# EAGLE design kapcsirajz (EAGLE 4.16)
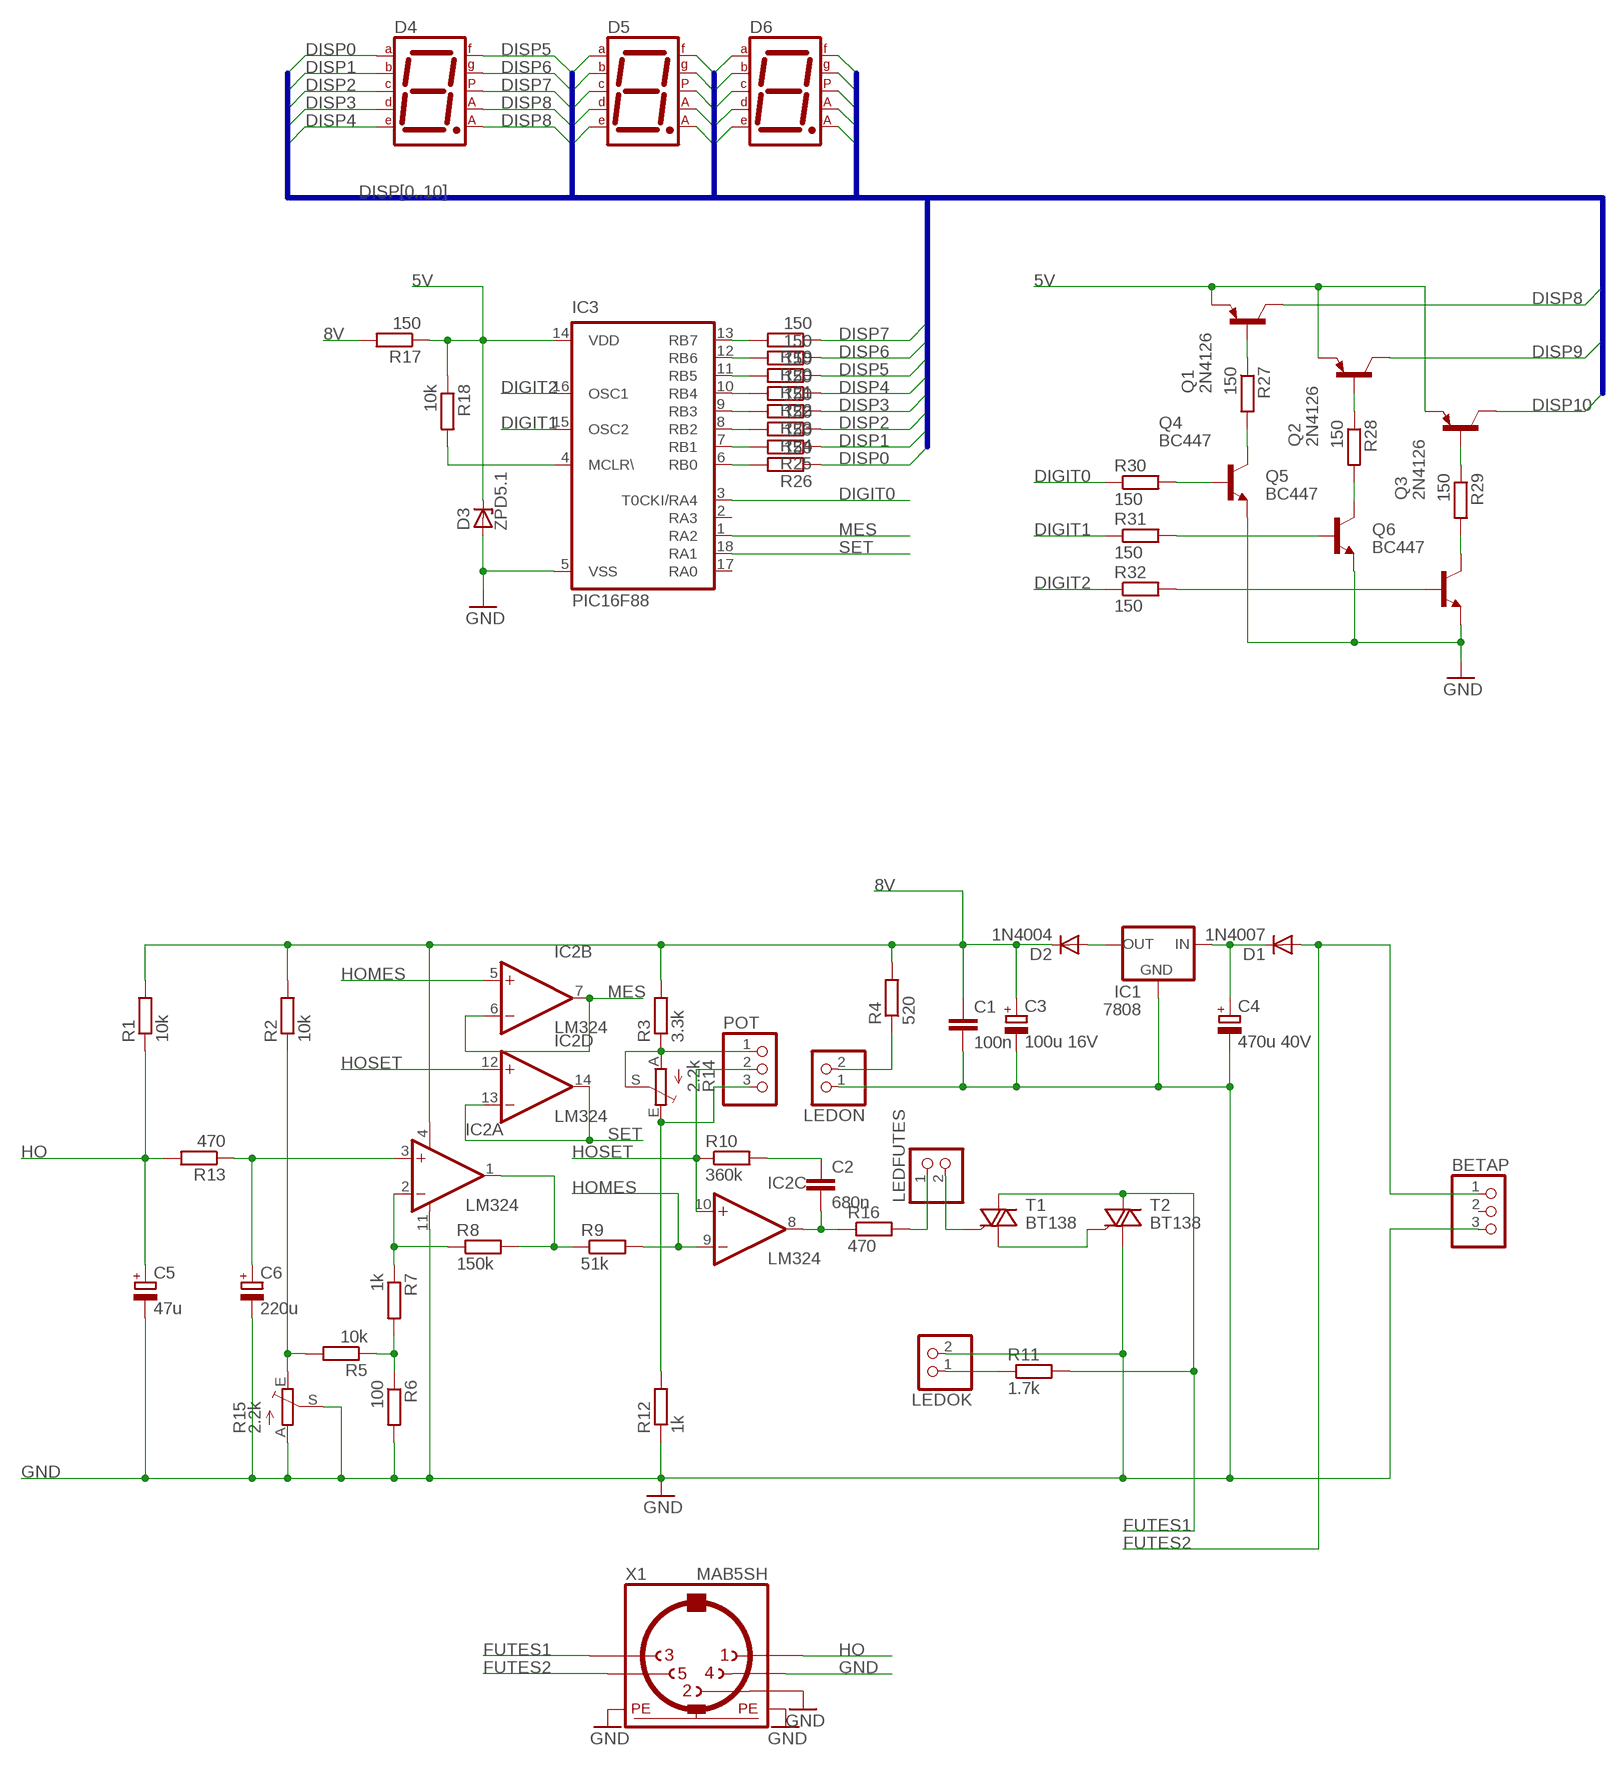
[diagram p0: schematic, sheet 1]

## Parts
BETAP  PINHD-1X3  [1X03]
C1  100n  C-EU025-025X050  [C025-025X050]
C2  680n  C-EU025-025X050  [C025-025X050]
C3  100u 16V  CPOL-EUE2,5-6E  [E2,5-6E]
C4  470u 40V  CPOL-EUE2,5-6E  [E2,5-6E]
C5  47u  CPOL-EUE2,5-6E  [E2,5-6E]
C6  220u  CPOL-EUE2,5-6E  [E2,5-6E]
D1  1N4007  1N4148  [DO35-10]
D2  1N4004  1N4148  [DO35-10]
D3  ZPD5.1  BZD23  [SOD81]
D4  7SEG-CA  [7SEG-13]
D5  7SEG-CA  [7SEG-13]
D6  7SEG-CA  [7SEG-13]
IC1  7808  78XXL  [78XXL]
IC2  LM324  OPA4658UP  [DIL14]
IC3  PIC16F88  PIC16F83SO  [SO-18W]
LEDFUTES  PINHD-1X2  [1X02]
LEDOK  PINHD-1X2  [1X02]
LEDON  PINHD-1X2  [1X02]
POT  PINHD-1X3  [1X03]
Q1  2N4126  [TO92-CBE]
Q2  2N4126  [TO92-CBE]
Q3  2N4126  [TO92-CBE]
Q4  BC447  [TO92-EBC]
Q5  BC447  [TO92-EBC]
Q6  BC447  [TO92-EBC]
R1  10k  R-EU_0204/7  [0204/7]
R2  10k  R-EU_0204/7  [0204/7]
R3  3.3k  R-EU_0204/7  [0204/7]
R4  520  R-EU_0204/7  [0204/7]
R5  10k  R-EU_0204/7  [0204/7]
R6  100  R-EU_0204/7  [0204/7]
R7  1k  R-EU_0204/7  [0204/7]
R8  150k  R-EU_0204/7  [0204/7]
R9  51k  R-EU_0204/7  [0204/7]
R10  360k  R-EU_0204/7  [0204/7]
R11  1.7k  R-EU_0204/7  [0204/7]
R12  1k  R-EU_0204/7  [0204/7]
R13  470  R-EU_0204/7  [0204/7]
R14  2.2k  TRIM_EU-CA6V  [CA6V]
R15  2.2k  TRIM_EU-CA6V  [CA6V]
R16  470  R-EU_0204/7  [0204/7]
R17  150  R-EU_0204/7  [0204/7]
R18  10k  R-EU_0204/7  [0204/7]
R19  150  R-EU_0204/7  [0204/7]
R20  150  R-EU_0204/7  [0204/7]
R21  150  R-EU_0204/7  [0204/7]
R22  150  R-EU_0204/7  [0204/7]
R23  150  R-EU_0204/7  [0204/7]
R24  150  R-EU_0204/7  [0204/7]
R25  150  R-EU_0204/7  [0204/7]
R26  150  R-EU_0204/7  [0204/7]
R27  150  R-EU_0204/7  [0204/7]
R28  150  R-EU_0204/7  [0204/7]
R29  150  R-EU_0204/7  [0204/7]
R30  150  R-EU_0204/7  [0204/7]
R31  150  R-EU_0204/7  [0204/7]
R32  150  R-EU_0204/7  [0204/7]
T1  BT138  TIC225S  [TO220DS]
T2  BT138  TIC225S  [TO220DS]
X1  MAB5SH  [MAB5SH]

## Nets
5V: D3.C IC3.14(VDD) Q1.E Q2.E Q3.E R17.1 R18.1
8V: C1.1 C3.+ D2.C IC2.4(A:V+) R1.2 R2.2 R3.2 R4.2 R17.2
DIGIT0: IC3.3(T0CKI/RA4) R30.1
DIGIT1: IC3.15(OSC2) R31.1
DIGIT2: IC3.16(OSC1) R32.1
DISP0: D4.7(A) D5.7(A) D6.7(A) R26.1
DISP1: D4.6(B) D5.6(B) D6.6(B) R25.1
DISP2: D4.4(C) D5.4(C) D6.4(C) R24.1
DISP3: D4.2(D) D5.2(D) D6.2(D) R23.1
DISP4: D4.1(E) D5.1(E) D6.1(E) R22.1
DISP5: D4.9(F) D5.9(F) D6.9(F) R21.1
DISP6: D4.10(G) D5.10(G) D6.10(G) R20.1
DISP7: D4.5(DP) D5.5(DP) D6.5(DP) R19.1
DISP8: D4.3(CA1) D4.8(CA2) Q1.C
DISP9: D5.3(CA1) D5.8(CA2) Q2.C
DISP10: D6.3(CA1) D6.8(CA2) Q3.C
FUTES1: R11.2 T1.A2 T2.A2 X1.3
FUTES2: BETAP.1 D1.A X1.5
GND: BETAP.3 C1.2 C3.- C4.- C5.- C6.- D3.A IC1.GND IC2.11(A:V-) IC3.5(VSS) LEDOK.2 LEDON.1 Q4.E Q5.E Q6.E R6.2 R12.1 R15.A R15.S T2.A1 X1.2 X1.4 X1.PE X1.PE@(PE)
HO: C5.+ R1.1 R13.2 X1.1
HOMES: IC2.5(B:+IN) IC2.9(C:-IN) R9.2
HOSET: IC2.10(C:+IN) IC2.12(D:+IN) POT.2 R10.1
MES: IC2.6(B:-IN) IC2.7(B:OUT) IC3.1(RA2)
N$1: D2.A IC1.OUT
N$2: C4.+ D1.C IC1.IN
N$3: IC3.4(MCLR\) R18.2
N$4: T1.A1 T2.G
N$5: IC3.13(RB7) R19.2
N$6: POT.1 R3.1 R14.A R14.S
N$7: LEDON.2 R4.1
N$8: POT.3 R12.2 R14.E
N$9: IC2.1(A:OUT) R8.2 R9.1
N$10: IC2.2(A:-IN) R7.1 R8.1
N$11: IC3.12(RB6) R20.2
N$12: R2.1 R5.2 R15.E
N$13: R5.1 R6.1 R7.2
N$14: C6.+ IC2.3(A:+IN) R13.1
N$15: IC3.11(RB5) R21.2
N$16: IC3.10(RB4) R22.2
N$17: C2.2 IC2.8(C:OUT) R16.1
N$18: C2.1 R10.2
N$19: LEDFUTES.1 R16.2
N$20: LEDFUTES.2 T1.G
N$21: IC3.9(RB3) R23.2
N$23: IC3.8(RB2) R24.2
N$24: LEDOK.1 R11.1
N$25: IC3.7(RB1) R25.2
N$26: IC3.6(RB0) R26.2
N$29: Q4.B R30.2
N$30: Q5.B R31.2
N$31: Q6.B R32.2
N$33: Q4.C R27.2
N$34: Q5.C R28.2
N$35: Q6.C R29.2
N$36: Q3.B R29.1
N$37: Q2.B R28.1
N$38: Q1.B R27.1
SET: IC2.13(D:-IN) IC2.14(D:OUT) IC3.18(RA1)
Unconnected: BETAP.2 IC3.2(RA3) IC3.17(RA0)

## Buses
DISP[0..10]

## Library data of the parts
BETAP POT = pinhead:PINHD-1X3: PIN HEADER
C1 C2 = rcl:C-EU: CAPACITOR, European symbol
C3-C6 = rcl:CPOL-EU: POLARIZED CAPACITOR, European symbol
D1 D2 = diode:1N4148: DIODE
D3 = diode:BZD23: Z DIODE
D4-D6 = special:7SEG-CA: 7-segment DISPLAY single anode, 13 mm
IC1 = v-reg:78XXL: VOLTAGE REGULATOR
IC2 = burr-brown:OPA4658U: Operational Amplifier
IC3 = microchip:PIC16F8*: MICROCONTROLLER 8-Bit PIC16F8X Family - CMOS Flash/EEPROM Pin Compatible : PIC16F83, PIC16CR83, PIC16F84A, PIC16CR84 see also PIC16C*
LEDFUTES LEDOK LEDON = pinhead:PINHD-1X2: PIN HEADER
Q1-Q3 = transistor-pnp:2N4126*: PNP Transistror
Q4-Q6 = transistor-npn:BC447*: NPN Transistor
R1-R13 R16-R32 = rcl:R-EU_: RESISTOR, European symbol
R14 R15 = pot:TRIM_EU-: POTENTIOMETER
T1 T2 = triac:TIC225S: TRIAC
X1 = con-hirschmann:MAB5SH: Female CONNECTOR 5 pins 90 deg. with shield, horizontal (DIN 41524)

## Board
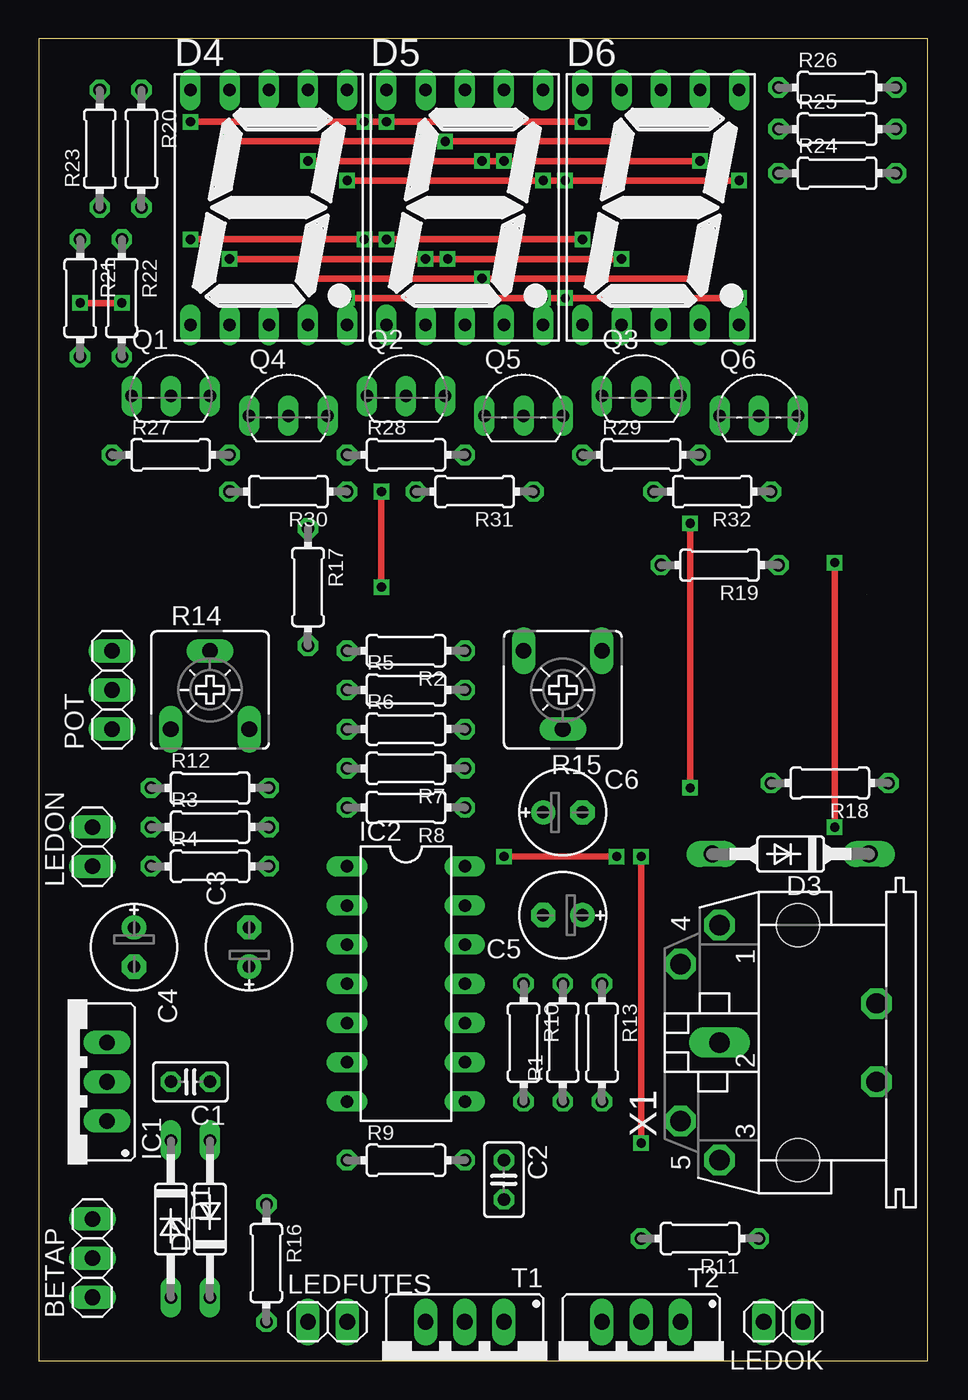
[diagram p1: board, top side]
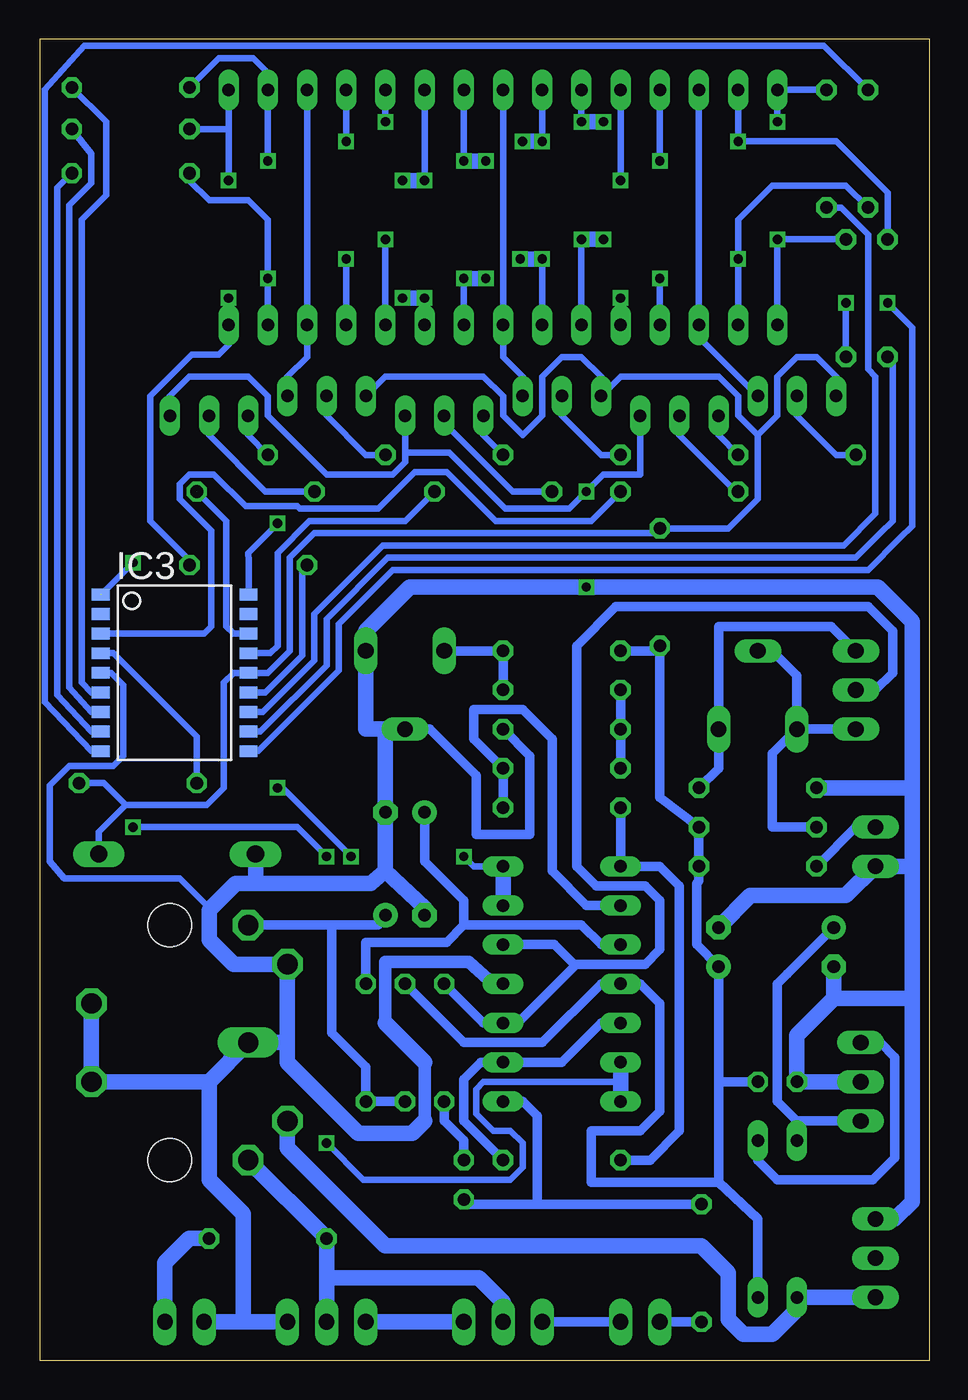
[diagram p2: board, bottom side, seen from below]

Size 57.61 x 85.71 mm. Coordinates in mm from the lower left corner, seen from the top.
Outline: 0,0 57.61,0 57.61,85.71 0,85.71 0,0
Copper layers (1*16): Top 0.035mm / dielectric 1.5mm / Bottom 0.035mm
Design rules "default": minimum track width 10mil, minimum drill 24mil, track to track 8mil, track to pad 8mil, pad to pad 8mil, via to via 8mil, smd to smd 8mil, copper to edge 40mil, drill to drill 8mil, minimum pad ring 10mil, minimum via ring 8mil, stop-mask expansion 4mil, vias tented up to drill 0mil, thermal gap 10mil

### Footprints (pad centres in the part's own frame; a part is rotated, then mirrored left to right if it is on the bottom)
1X03 = drill 1.016 long: 1 -2.54,0; 2 0,0; 3 2.54,0
C025-025X050 = drill 0.813 octagon: 1 -1.27,0; 2 1.27,0
E2,5-6E = drill 0.813 pad 1.575 round: + -1.27,0 | drill 0.813 pad 1.575 octagon: - 1.27,0
DO35-10 = drill 0.813 long: A 5.08,0; C -5.08,0
SOD81 = drill 1.118 long: A 5.08,0; C -5.08,0
7SEG-13 = drill 0.813 long: 1 -5.08,-7.62; 2 -2.54,-7.62; 3 0,-7.62; 4 2.54,-7.62; 5 5.08,-7.62; 6 5.08,7.62; 7 2.54,7.62; 8 0,7.62; 9 -2.54,7.62; 10 -5.08,7.62
78XXS = drill 1.016 long: GND 0,-2.54; IN -2.54,-2.54; OUT 2.54,-2.54
DIL14 = drill 0.813 long: 1 -7.62,-3.81; 2 -5.08,-3.81; 3 -2.54,-3.81; 4 0,-3.81; 5 2.54,-3.81; 6 5.08,-3.81; 7 7.62,-3.81; 8 7.62,3.81; 9 5.08,3.81; 10 2.54,3.81; 11 0,3.81; 12 -2.54,3.81; 13 -5.08,3.81; 14 -7.62,3.81
SO-18W = smd 0.762 x 1.143: 1 -5.08,-4.788; 2 -3.81,-4.788; 3 -2.54,-4.788; 4 -1.27,-4.788; 5 0,-4.788; 6 1.27,-4.788; 7 2.54,-4.788; 8 3.81,-4.788; 9 5.08,-4.788; 10 5.08,4.788; 11 3.81,4.788; 12 2.54,4.788; 13 1.27,4.788; 14 0,4.788; 15 -1.27,4.788; 16 -2.54,4.788; 17 -3.81,4.788; 18 -5.08,4.788
1X02 = drill 1.016 long: 1 -1.27,0; 2 1.27,0
TO92-CBE = drill 0.813 long: B 0,0; C 2.54,0; E -2.54,0
TO92-EBC = drill 0.813 long: B 0,-1.27; C -2.54,-1.27; E 2.54,-1.27
0204/7 = drill 0.813 octagon: 1 -3.81,0; 2 3.81,0
CA6V = drill 1.016 long: A -2.54,-2.54; E 2.54,-2.54; S 0,2.54
TO220DS = drill 1.016 long: A1 -2.54,-2.54; A2 0,-2.54; G 2.54,-2.54
MAB5SH = drill 1.321 octagon: 1 7.62,5.08; 3 -7.62,5.08; 4 5.08,7.62; 5 -5.08,7.62; PE -2.54,-5.08; PE@ 2.54,-5.08 | drill 1.321 long: 2 0,5.08 | hole 2.794: 7.62,0; -7.62,0

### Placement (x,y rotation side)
BETAP  3.49,6.66 90 top
C1  9.84,18.09 180 top
C2  30.16,11.74 270 top
C3  13.65,26.82 90 top
C4  6.19,26.82 270 top
C5  33.97,28.89 180 top
C6  33.97,35.55 0 top
D1  8.57,9.2 270 top
D2  11.11,9.2 90 top
D3  48.73,32.86 180 top
D4  14.92,74.77 0 top
D5  27.62,74.77 0 top
D6  40.32,74.77 0 top
IC1  7808  [78XXS]  1.9,18.09 90 top
IC2  23.81,24.44 270 top
IC3  48.89,44.6 270 bottom
LEDFUTES  18.73,2.54 0 top
LEDOK  48.25,2.54 180 top
LEDON  3.49,33.33 90 top
POT  4.76,43.49 90 top
Q1  8.57,62.54 0 top
Q2  23.81,62.54 0 top
Q3  39.05,62.54 0 top
Q4  16.19,62.54 0 top
Q5  31.43,62.54 0 top
Q6  46.67,62.54 0 top
R1  33.97,20.63 90 top
R2  23.81,46.03 180 top
R3  11.11,34.6 0 top
R4  11.11,32.06 0 top
R5  23.81,43.49 0 top
R6  23.81,40.95 0 top
R7  23.81,38.41 180 top
R8  23.81,35.87 180 top
R9  23.81,13.01 0 top
R10  31.43,20.63 270 top
R11  42.86,7.93 180 top
R12  11.11,37.14 0 top
R13  36.51,20.63 270 top
R14  11.11,43.49 0 top
R15  33.97,43.49 180 top
R16  14.76,6.35 270 top
R17  17.46,50.16 270 top
R18  51.27,37.46 180 top
R19  44.13,51.59 180 top
R20  6.66,78.58 270 top
R21  2.69,68.89 270 top
R22  5.39,68.89 270 top
R23  3.96,78.58 90 top
R24  51.75,76.99 0 top
R25  51.75,79.85 0 top
R26  51.75,82.55 0 top
R27  8.57,58.73 0 top
R28  23.81,58.73 0 top
R29  39.05,58.73 0 top
R30  16.19,56.35 180 top
R31  28.25,56.35 180 top
R32  43.65,56.35 180 top
T1  27.62,0 180 top
T2  39.05,0 180 top
X1  49.21,20.63 90 top

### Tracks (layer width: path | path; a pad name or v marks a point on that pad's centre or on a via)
5V
  Bottom 0.406: 52.06,36.03 46.83,36.03 45.71,37.14 45.71,43.97 45.08,44.6 IC3.14 42.86,44.6 41.43,46.03 41.43,52.07 39.84,53.65 17.77,53.65 R17.1 | 52.06,36.03 53.81,34.29 D3.C | R17.1 | R18.1 53.49,37.46 52.06,36.03 | Q1.E 6.03,63.81 7.3,65.08 8.57,65.08 9.84,63.81 9.84,61.27 11.11,60 | Q3.E 35.24,63.81 28.89,63.81 27.62,62.54 27.62,61.27 26.35,60 25.08,61.27 25.08,63.81 23.81,65.08 22.54,65.08 21.27,63.81 Q2.E 20,63.81 13.65,63.81 12.38,62.54 12.38,61.27 11.11,60 | R17.1 13.01,53.97 11.11,55.87 11.11,60
8V
  Bottom 0.61: R1.2 30.16,20.63 25.08,20.63 21.27,24.44 IC2.4 18.73,24.44 17.46,23.17 17.46,16.19 18.73,14.92 21.9,14.92 21.9,11.58 13.65,11.58 | 13.65,11.58 11.11,9.2 D2.C | 13.65,11.58 13.65,18.09 | 13.65,18.09 C1.1 | R2.2 17.46,46.03 17.46,45.87 | 17.46,45.87 17.46,36.51 R3.2 R4.2 14.92,31.11 15.08,30.95 15.08,26.98 C3.+ 13.65,18.09 | 17.46,45.87 R17.2 | 17.46,45.87
DIGIT0
  Bottom 0.406: IC3.3 46.98,47.14 46.51,47.62 46.51,53.81 48.57,55.87 48.57,56.83 48.41,56.99 | R30.1 21.9,54.45 28.09,54.45 31.27,57.62 33.33,57.62 34.44,56.51 | 48.41,56.99 | 48.41,56.99 47.94,57.46 46.35,57.46 44.29,55.4 40.95,55.4 40.79,55.24 35.71,55.24 34.44,56.51 | 34.44,56.51
DIGIT1  (1 unrouted)
  Bottom 0.406: 42.22,47.94 42.22,47.78 42.22,47.46 42.22,46.35 42.7,45.87 IC3.15 | 42.22,47.94 | 42.22,47.94 42.22,52.38 40.16,54.45 33.97,54.45 32.7,55.72 R31.1 31.9,56.51
DIGIT2  (1 unrouted)
  Bottom 0.406: R32.1 45.56,54.45 45.56,47.62 45.08,47.14 IC3.16
DISP0  (via drill 0.6)
  Top 0.406: v17.46,77.78 v28.73,77.78 v30.16,77.78 v42.86,77.78
  Bottom 0.406: v17.46,77.78 D4.7 | v17.46,77.78 | v42.86,77.78 D6.7 42.86,83.5 43.81,84.45 46.03,84.45 R26.1 | R26.1 | v30.16,77.78 D5.7 v30.16,77.78
  Bottom 1.016: v28.73,77.78 v30.16,77.78
DISP1  (via drill 0.6)
  Top 0.406: v20,76.51 v32.7,76.51 v34.13,76.51 v45.4,76.51
  Bottom 0.406: v20,76.51 D4.6 | v20,76.51 | v45.4,76.51 45.4,79.85 | 45.4,79.85 D6.6 | 45.4,79.85 R25.1 | 45.4,79.85 | v32.7,76.51 D5.6 v32.7,76.51
  Bottom 1.016: v32.7,76.51 v34.13,76.51
DISP2  (via drill 0.6)
  Top 0.406: v17.46,70.16 v28.73,70.16 v30.16,70.16 v42.86,70.16
  Bottom 0.406: D4.4 v17.46,70.16 | v17.46,70.16 | D6.4 v42.86,70.16 42.86,73.97 44.13,75.24 46.67,75.24 47.94,76.51 R24.1 | v30.16,70.16 D5.4 v30.16,70.16
  Bottom 1.016: v28.73,70.16 v30.16,70.16
DISP3  (via drill 0.6)
  Top 0.406: v12.38,71.43 v25.08,71.43 v26.51,71.43 v37.78,71.43
  Bottom 0.406: D4.2 v12.38,71.43 | v12.38,71.43 | v37.78,71.43 D6.2 | v12.38,71.43 12.38,73.97 11.27,75.08 | 11.27,75.08 | R23.1 | R23.1 5.39,76.19 10.15,76.19 11.27,75.08 | v25.08,71.43 D5.2 v25.08,71.43
  Bottom 1.016: v25.08,71.43 v26.51,71.43
DISP4  (via drill 0.6)
  Top 0.406: v9.84,72.7 v21.11,72.7 v22.54,72.7 v35.24,72.7
  Bottom 0.406: D4.1 v9.84,72.7 | v9.84,72.7 | v35.24,72.7 D6.1 | v9.84,72.7 8.88,72.7 | R22.1 8.88,72.7 | 8.88,72.7 | v22.54,72.7 D5.1 v22.54,72.7
  Bottom 1.016: v21.11,72.7 v22.54,72.7
DISP5  (via drill 0.6)
  Top 0.406: v12.38,79.05 v25.08,79.05 v26.35,79.05 v37.78,79.05
  Bottom 0.406: v12.38,79.05 D4.9 | v12.38,79.05 | v37.78,79.05 D6.9 | R21.1 2.69,75.72 6.03,79.05 v12.38,79.05 | v25.08,79.05 D5.9 v25.08,79.05
  Bottom 1.016: v25.08,79.05 v26.35,79.05
DISP6  (via drill 0.6)
  Top 0.406: v9.84,80.32 v21.11,80.32 v22.54,80.32 v35.24,80.32
  Bottom 0.406: 9.84,81.59 D4.10 9.84,82.23 | 9.84,81.59 v9.84,80.32 | v9.84,80.32 | v35.24,80.32 D6.10 | 9.84,81.59 | 9.84,82.23 | R20.1 9.68,82.39 9.84,82.23 | v22.54,80.32 D5.10 v22.54,80.32
  Bottom 1.016: 22.38,80.32 v21.11,80.32 v22.54,80.32
DISP7  (via drill 0.6)
  Top 0.406: v20,68.89 v32.7,68.89 v34.13,68.89 v45.4,68.89
  Bottom 0.406: D4.5 v20,68.89 | v20,68.89 | v45.4,68.89 D6.5 | D6.5 45.4,66.99 | 45.4,66.67 45.4,66.99 | 45.4,66.67 45.4,66.51 | 45.4,66.99 | R19.1 47.94,51.91 50.48,54.45 50.48,62.54 47.78,65.24 46.03,65.24 45.4,65.88 45.4,66.67 | D6.5 45.4,66.67 | v32.7,68.89 D5.5 v32.7,68.89
  Bottom 1.016: v32.7,68.89 v34.13,68.89
DISP8
  Bottom 0.406: 14.92,67.62 14.92,66.35 Q1.C | 14.92,67.62 | 14.92,67.62 D4.3 | 14.92,67.62 D4.8 | 14.92,67.62
DISP9
  Bottom 0.406: D5.3 27.62,67.62 | D5.3 D5.8 | Q2.C 26.35,63.81 27.62,65.08 D5.3
DISP10
  Bottom 0.406: D6.8 D6.3 40.32,65.08 41.59,63.81 Q3.C
FUTES1
  Bottom 1.016: X1.3 R11.2 39.05,5.71 | T1.A2 27.62,3.81 29.2,5.39 39.05,5.39 39.05,5.71 | 39.05,5.71 T2.A2
FUTES2
  Bottom 1.016: BETAP.1 D1.A 8.57,3.33 10.15,1.74 12.06,1.74 13.01,2.69 13.01,5.71 14.76,7.46 35.24,7.46 41.59,13.81 X1.5
GND  (via drill 0.6)
  Top 0.406: v22.22,50.16 v22.22,56.35
  Bottom 0.406: 46.59,29.28 48.57,31.27 56.03,31.27 56.99,32.38 56.99,37.3 55.72,38.57 52.86,38.57 52.22,39.21 52.22,43.81 53.02,44.6 IC3.5 | Q6.E 49.21,62.54 47.94,63.81 44.13,63.81 42.86,62.54 42.86,61.27 39.05,57.46 34.76,57.46 33.97,58.26 33.97,58.89 | 33.97,58.89 Q5.E | Q4.E 18.73,57.46 21.11,57.46 v22.22,56.35 23.33,55.24 27.46,55.24 31.11,58.89 33.97,58.89
  Bottom 0.61: R15.S 32.38,40.95 29.36,37.94 29.36,34.13 25.87,34.13 25.87,39.21 R6.2 | 46.59,29.28
  Bottom 0.813: 35.24,21.9 35.24,25.87 29.84,25.87 28.25,24.44 IC2.11 | 32.7,15.55 32.7,19.36
  Bottom 1.016: 1.11,37.14 R12.1 | 1.11,32.06 1.11,37.14 | BETAP.3 2.22,9.2 1.11,10.31 1.11,23.49 | 1.11,23.49 6.19,23.49 | 6.19,23.49 8.57,21.11 C1.2 IC1.GND | 1.11,23.49 1.11,32.06 | 35.24,40.95 36.51,40.95 R15.A 36.51,47.3 33.65,50.16 v22.22,50.16 3.33,50.16 1.11,47.94 1.11,37.14 | 35.24,40.95 C6.- 35.24,31.75 | 35.24,40.95 R15.S | X1.PE@ X1.PE 46.67,18.09 | 44.6,2.54 44.44,2.54 44.44,9.52 46.67,11.74 46.67,18.09 | 44.6,2.54 LEDOK.2 | 41.59,20.63 41.59,19.36 36.98,14.76 | 36.98,14.76 | 36.98,14.76 33.49,14.76 32.7,15.55 | 32.7,19.36 35.24,21.9 | 41.59,20.63 X1.4 45.08,25.71 46.67,27.3 46.67,29.21 46.59,29.28 44.92,30.95 | 41.59,20.63 X1.2 46.67,18.09 | 44.6,2.54 T2.A1 | 43.65,30.95 D3.A | 44.92,30.95 | 44.92,30.95 44.44,30.95 43.65,30.95 | 1.11,32.06 3.17,32.06 3.33,31.9 LEDON.1 5.39,30.16 11.58,30.16 C3.- | C4.- 6.19,23.49 | C5.- 32.7,29.36 35.24,31.75 | 35.24,31.75 36.19,30.95 43.65,30.95
HO
  Bottom 0.61: R1.1 R13.2 36.51,19.04 38.73,21.27 38.73,28.25 | 38.73,28.25 X1.1 | X1.1 | 38.73,28.25 35.71,28.25 C5.+ | C5.+
HOMES
  Bottom 0.61: R9.2 30.16,15.55 30.16,18.25 29.05,19.36 IC2.9 23.81,19.36 21.27,21.9 IC2.5 19.68,21.9
HOSET
  Bottom 0.61: R10.1 28.89,21.9 IC2.10 26.66,21.9 22.85,25.71 | 22.85,25.71 18.41,25.71 17.46,26.66 17.46,29.84 18.41,30.79 21.58,30.79 22.85,32.06 22.85,46.35 20.31,48.89 3.96,48.89 2.38,47.3 2.38,44.6 3.49,43.49 POT.2 | 22.85,25.71 23.01,25.71 24.28,26.98 IC2.12
MES  (via drill 0.6)  (1 unrouted)
  Top 0.406: v51.59,34.6 v51.59,51.75 | v39.05,32.7 39.05,14.76 v39.05,14.12
  Bottom 0.406: v51.59,51.75 53.65,49.68 | v51.59,34.6 47.62,34.6 40.95,34.6 v39.05,32.7 | v39.05,14.12 36.67,11.74 27.14,11.74 26.35,12.54 26.35,14.12 27.14,14.92 28.25,14.92 29.36,16.03 29.36,17.62 28.89,18.09 20,18.09
  Bottom 1.016: IC2.7 20,18.09 IC2.6
N$1
  Bottom 0.61: D2.A 11.11,13.01 9.84,11.74 3.65,11.74 2.22,13.17 2.22,19.68 3.17,20.63 IC1.OUT
N$2
  Bottom 0.61: IC1.IN 8.57,15.55 | 8.57,15.55 9.84,16.82 9.84,24.44 9.2,25.08 C4.+ | 8.57,15.55 D1.C | C4.+
N$3
  Bottom 0.406: R18.2 47.46,40.48 52.86,45.87 IC3.4
N$4
  Bottom 1.016: T1.A1 T2.G
N$5
  Bottom 0.406: IC3.13 43.02,43.33 40.63,45.72 40.63,51.27 R19.2 | R19.2
N$6
  Bottom 0.61: R3.1 10.15,34.6 10.15,39.36 R14.A | R14.A POT.1 | R14.S 10.15,46.03 8.57,44.44 R14.A
N$7
  Bottom 0.61: R4.1 4.76,34.6 LEDON.2
N$8
  Bottom 0.61: R12.2 13.65,38.41 R14.E 13.65,47.62 6.34,47.62 POT.3
N$9
  Bottom 0.61: R9.1 18.09,13.01 16.19,14.92 16.19,30.79 17.46,32.06 IC2.1 R8.2
N$10
  Bottom 0.61: IC2.2 22.22,29.52 24.44,31.75 24.44,40.32 26.35,42.22 29.52,42.22 29.52,40.32 R7.1 R8.1
N$11
  Bottom 0.406: 44.13,42.06 IC3.12 43.17,42.06 39.84,45.4 39.84,48.41 35.4,52.86 5.55,52.86 3.49,54.92 3.49,63.81 3.96,64.29 3.96,73.02 5.71,74.77 R20.2
N$12
  Bottom 0.61: R5.2 R2.1 R15.E
N$13
  Bottom 0.61: R7.2 R6.1 R5.1
N$14
  Bottom 0.61: 30.16,28.25 22.54,28.25 21.27,26.98 IC2.3 | 30.16,28.25 30.16,29.84 32.7,32.38 C6.+ | R13.1 36.51,27.14 31.27,27.14 30.16,28.25
N$15
  Bottom 0.406: 44.13,40.79 IC3.11 43.33,40.79 39.05,45.08 39.05,48.1 35.08,52.07 4.76,52.07 3.17,53.65 2.38,54.45 2.38,64.76 R21.2
N$16  (via drill 0.6)
  Top 0.406: v2.69,68.58 v5.39,68.58
  Bottom 0.406: 1.9,53.34 3.96,51.27 34.76,51.27 38.25,47.78 38.25,44.76 43.49,39.52 IC3.10 44.13,39.52 | 1.9,53.34 | 1.9,53.34 1.11,54.13 1.11,66.99 v2.69,68.58 | R22.2 | v5.39,68.58 R22.2
N$17
  Bottom 0.61: IC2.8 26.35,16.82 25.39,15.87 25.39,10.15 | R16.1 25.39,10.15 | 25.39,10.15 29.84,10.15 C2.2
N$18
  Bottom 0.61: C2.1 30.16,14.28 31.43,15.55 R10.2
N$19
  Bottom 0.61: R16.2 LEDFUTES.1
N$20
  Bottom 0.61: LEDFUTES.2 T1.G
N$21
  Bottom 0.406: IC3.9 54.29,39.52 57.3,42.7 57.3,45.08 57.3,82.39 54.76,85.24 6.82,85.24 R23.2 | R23.2
N$23
  Bottom 0.406: R24.2 | R24.2 56.51,76.04 56.51,43.18 54.29,40.79 IC3.8 53.65,40.79
N$24
  Bottom 1.016: R11.1 47.94,7.93 49.52,6.35 LEDOK.1
N$25
  Bottom 0.406: IC3.7 54.29,42.06 55.72,43.65 55.72,45.24 55.72,74.29 55.72,74.93 55.08,75.56 54.29,76.35 54.29,78.26 R25.2
N$26
  Bottom 0.406: IC3.6 54.29,43.33 54.92,43.97 54.92,73.97 53.33,75.56 53.33,80.32 R26.2 | R26.2
N$29
  Bottom 0.406: R30.2 12.54,56.35 16.19,60 Q4.B
N$30
  Bottom 0.406: R31.2 26.98,56.35 31.27,60.64 | Q5.B 31.43,60.8 31.27,60.64 | 31.27,60.64
N$31
  Bottom 0.406: R32.2 43.02,56.35 46.67,60 Q6.B | Q6.B
N$33
  Bottom 0.406: R27.2 13.65,60 Q4.C
N$34
  Bottom 0.406: R28.2 28.89,60 Q5.C
N$35
  Bottom 0.406: R29.2 44.13,60 Q6.C | Q6.C
N$36
  Bottom 0.406: R29.1 36.51,58.73 39.05,61.27 Q3.B
N$37
  Bottom 0.406: R28.1 21.27,58.73 23.81,61.27 Q2.B
N$38
  Bottom 0.406: R27.1 6.03,58.73 8.57,61.27 Q1.B
SET  (via drill 0.6)
  Top 0.406: v30.16,32.7 v37.46,32.7 | v42.22,37.14 v42.22,54.29
  Bottom 0.406: IC2.14 29.52,32.06 v30.16,32.7 | v37.46,32.7 41.9,37.14 v42.22,37.14 | v42.22,54.29 44.13,52.38 44.1,51.88 IC3.18
  Bottom 1.016: IC2.13 IC2.14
